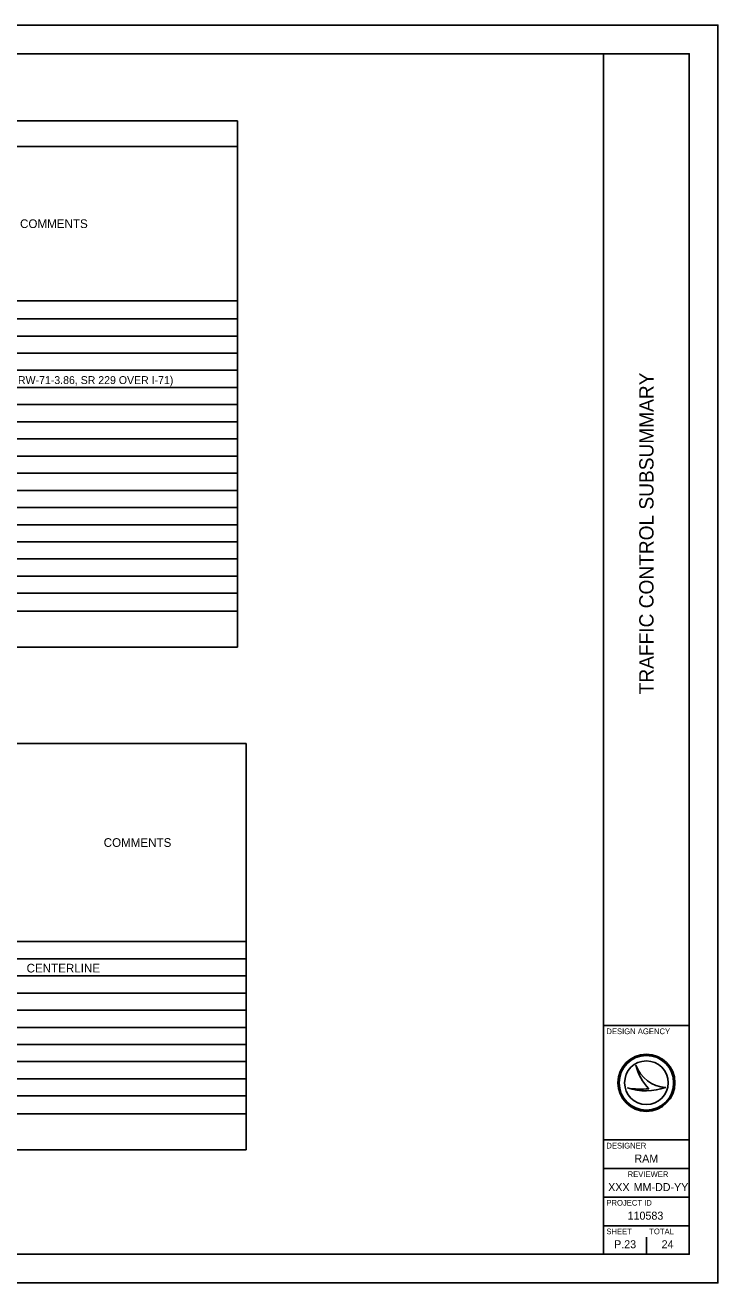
# Model space of a CAD drawing. Extents: x 0 to 34, y 0 to 22.
# Drawn here: x 21.88 to 34, y 0 to 22 of the extents above; entities that cross this region are included whole.
import ezdxf

# ---------------------------------------------------------------- set-up
doc = ezdxf.new("R2010")
doc.units = 0
for name, color, linetype in [('Default', 7, 'Continuous'), ('SH_Border', 7, 'Continuous'), ('SH_Cut_Line', 7, 'Continuous'), ('SH_Data', 7, 'Continuous'), ('SH_Text', 7, 'Continuous')]:
    doc.layers.add(name, color=color, linetype=linetype)

msp = doc.modelspace()

# ---------------------------------------------------------------- linework, layer by layer
at = {"layer": 'Default'}
for p, q in [((6.022, 20.327), (25.597, 20.327)), ((25.597, 20.327), (25.597, 11.117)), ((6.022, 19.877), (25.597, 19.877)), ((11.542, 17.177), (25.597, 17.177)), ((6.022, 16.862), (25.597, 16.862)), ((6.022, 16.562), (25.597, 16.562)), ((6.022, 16.262), (25.597, 16.262)), ((6.022, 15.962), (25.597, 15.962)), ((6.022, 15.662), (25.597, 15.662)), ((6.022, 15.362), (25.597, 15.362)), ((6.022, 15.062), (25.597, 15.062)), ((6.022, 14.762), (25.597, 14.762)), ((6.022, 14.462), (25.597, 14.462)), ((6.022, 14.162), (25.597, 14.162)), ((6.022, 13.862), (25.597, 13.862)), ((6.022, 13.562), (25.597, 13.562)), ((6.022, 13.262), (25.597, 13.262)), ((6.022, 12.962), (25.597, 12.962)), ((6.022, 12.662), (25.597, 12.662)), ((6.022, 12.362), (25.597, 12.362)), ((6.022, 12.062), (25.597, 12.062)), ((6.022, 11.747), (25.597, 11.747)), ((6.022, 11.117), (25.597, 11.117))]:
    msp.add_line(p, q, dxfattribs=at)
at = {"layer": 'SH_Border'}
for p, q in [((32, 0.5), (32, 21.5)), ((32, 4.5), (33.5, 4.5)), ((32, 2.5), (33.5, 2.5)), ((32, 2), (33.5, 2)), ((32, 1.5), (33.5, 1.5)), ((32, 1), (33.5, 1))]:
    msp.add_line(p, q, dxfattribs=at)
msp.add_lwpolyline([(1.5, 21.5), (33.5, 21.5), (33.5, 0.5), (1.5, 0.5)], close=True, dxfattribs=at)
at = {"layer": 'SH_Cut_Line'}
msp.add_lwpolyline([(0, 0), (34, 0), (34, 22), (0, 22)], close=True, dxfattribs=at)
at = {"layer": 'SH_Data'}
for p, q in [((32.567, 3.81), (32.567, 3.81)), ((32.417, 3.41), (32.417, 3.41)), ((32.75, 3.5), (32.75, 3.5)), ((33.087, 3.419), (33.087, 3.419)), ((32.375, 0.675), (32.375, 0.675)), ((32.75, 0.5), (32.75, 0.8))]:
    msp.add_line(p, q, dxfattribs=at)
for radius in [0.5, 0.477, 0.477, 0.382]:
    msp.add_circle((32.75, 3.5), radius, dxfattribs=at)
for centre, radius, start, end in [((33.116, 3.998), 0.58, 198.9257, 198.9319), ((33.347, 3.97), 0.796, 191.6379, 191.6421), ((33.116, 3.998), 0.58, 198.9319, 267.1657), ((33.347, 3.97), 0.796, 191.6421, 226.0947), ((32.739, 4.37), 1.013, 251.4576, 290.0832), ((32.648, 4.654), 1.266, 259.4964, 259.4995), ((32.739, 4.37), 1.013, 251.4527, 251.4576), ((32.648, 4.654), 1.266, 259.4995, 276.6672)]:
    msp.add_arc(centre, radius, start, end, dxfattribs=at)
at = {"layer": 'SH_Text'}
for p, q in [((5.872, 9.434), (25.747, 9.434)), ((25.747, 9.434), (25.747, 2.324)), ((5.872, 5.969), (25.747, 5.969)), ((5.872, 5.669), (25.747, 5.669)), ((5.872, 5.369), (25.747, 5.369)), ((5.872, 5.069), (25.747, 5.069)), ((5.872, 4.769), (25.747, 4.769)), ((5.872, 4.469), (25.747, 4.469)), ((5.872, 4.169), (25.747, 4.169)), ((5.872, 3.869), (25.747, 3.869)), ((5.872, 3.569), (25.747, 3.569)), ((5.872, 3.269), (25.747, 3.269)), ((5.872, 2.954), (25.747, 2.954)), ((5.872, 2.324), (25.747, 2.324))]:
    msp.add_line(p, q, dxfattribs=at)

# ---------------------------------------------------------------- texts
at = {"layer": 'Default'}
for s, height, p in [('COMMENTS', 0.1518, (21.793, 18.451)), ('CONCRETE BRIDGE DECK (MRW-71-3.86, SR 229 OVER I-71)', 0.138, (19.132, 15.722))]:
    msp.add_text(s, height=height, dxfattribs=at).set_placement(p)
at = {"layer": 'SH_Data'}
msp.add_text('TRAFFIC CONTROL SUBSUMMARY', height=0.25, rotation=90, dxfattribs=at).set_placement((32.875, 10.295))
for s, height, p in [('DESIGN AGENCY', 0.1, (32.05, 4.35)), ('DESIGNER', 0.1, (32.05, 2.35)), ('RAM', 0.14, (32.541, 2.105)), ('REVIEWER', 0.1, (32.422, 1.85)), ('XXX', 0.14, (32.081, 1.605)), ('MM-DD-YY', 0.14, (32.527, 1.605)), ('PROJECT ID', 0.1, (32.05, 1.35)), ('110583', 0.14, (32.421, 1.105)), ('SHEET', 0.1, (32.05, 0.85)), ('TOTAL', 0.1, (32.8, 0.85)), ('P.23', 0.14, (32.185, 0.605)), ('24', 0.14, (33.016, 0.605))]:
    msp.add_text(s, height=height, dxfattribs=at).set_placement(p)
at = {"layer": 'SH_Text'}
for s, p in [('COMMENTS', (23.256, 7.626)), ('CENTERLINE', (21.907, 5.429))]:
    msp.add_text(s, height=0.1518, dxfattribs=at).set_placement(p)

doc.saveas('drawing.dxf')
